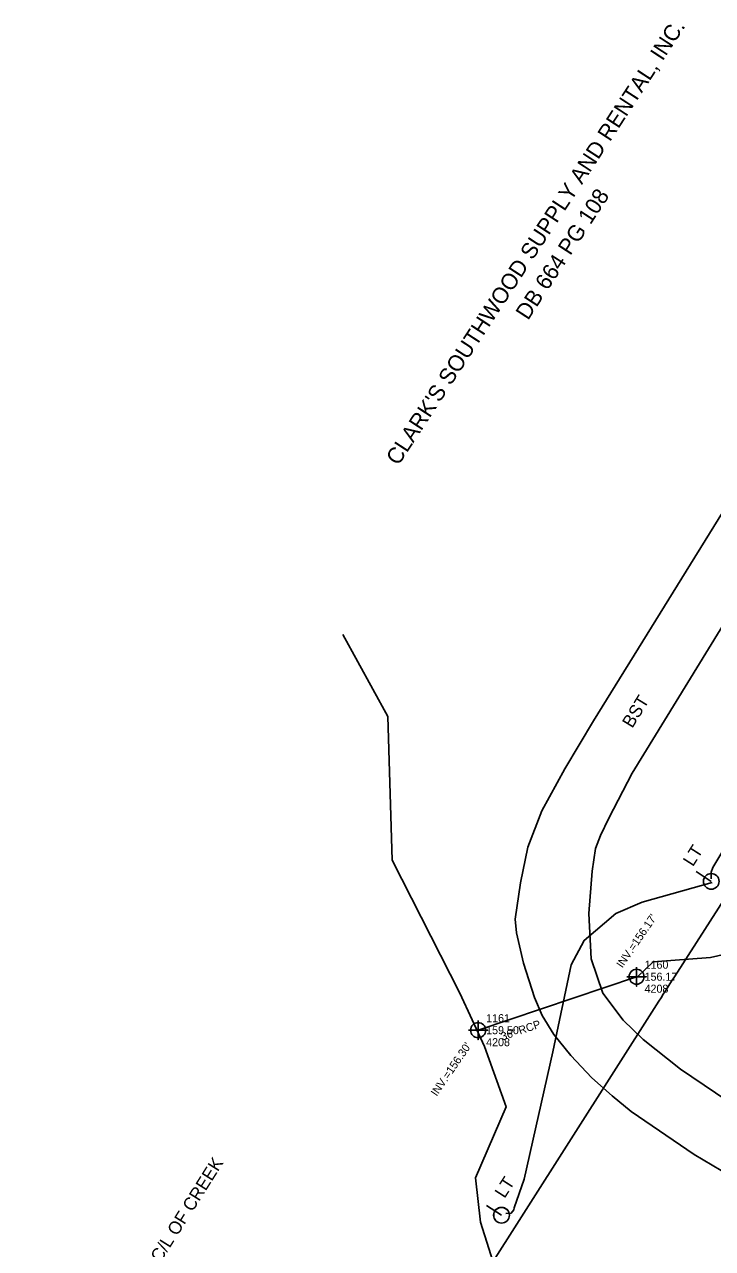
# Model space of a CAD drawing. Extents: x 1840200 to 1849051, y 348278 to 353012.
# Drawn here: x 1844547 to 1844762, y 350948.7 to 351331.2 of the extents above; entities that cross this region are included whole.
import ezdxf

# ---------------------------------------------------------------- set-up
doc = ezdxf.new("R2010")
doc.units = 0
for name, color, linetype in [('Default', 7, 'Continuous'), ('Exist Hydro Stream or Body of Water', 7, 'Continuous'), ('Exist Property Deed Book Text', 7, 'Continuous'), ('Exist Property Line Text', 7, 'Continuous'), ('Exist Property Owner Text', 7, 'Continuous'), ('Exist Right of Way Line', 7, 'Continuous'), ('Exist Roads EOP Other', 7, 'Continuous'), ('Exist Roads EOP Other Text', 7, 'Continuous'), ('Exist Structure Minor Pipes RCP 18 Inch SizeText', 7, 'Continuous'), ('Exist Structure Minor Pipes RCP 36 Inch', 7, 'Continuous'), ('Exist Structure Minor Pipes RCP 36 Inch Text', 7, 'Continuous'), ('Exist Structure Minor Pipes RCP 8 Inch Cogo Comment', 7, 'Continuous'), ('Exist Structure Minor Pipes RCP 8 Inch Cogo Elevation', 7, 'Continuous'), ('Exist Structure Minor Pipes RCP 8 Inch Cogo Number', 7, 'Continuous'), ('Exist Structure Minor Pipes RCP 8 Inch Cogo Point CELL', 7, 'Continuous'), ('Exist Utilities Other Pole CELL', 7, 'Continuous'), ('Exist Utilities Power Pole CELL', 7, 'Continuous'), ('Exist Utilities Power Pole Text', 7, 'Continuous'), ('Exist Utilities Power UG Cable SUE', 7, 'Continuous'), ('Exist Vegetation Woods Line', 7, 'Continuous')]:
    doc.layers.add(name, color=color, linetype=linetype)

# ---------------------------------------------------------------- blocks, each defined once
blk = doc.blocks.new('EXIST STRUCTURE MINOR PIPES RCP COGO POINT')
at = {"layer": 'Exist Structure Minor Pipes RCP 8 Inch Cogo Point CELL'}
blk.add_lwpolyline([(0, 0.06), (0, -0.06), (0, 0), (0.06, 0), (-0.06, 0)], dxfattribs=at)
blk.add_circle((0, 0), 0.0469, dxfattribs=at)
blk = doc.blocks.new('EXIST UTILITIES OTHER POLE')
at = {"layer": 'Exist Utilities Other Pole CELL'}
blk.add_circle((0, 0), 0.0493, dxfattribs=at)
blk = doc.blocks.new('EXIST UTILITIES POWER POLE')
at = {"layer": 'Exist Utilities Power Pole CELL'}
for q in [(0, 0.1125), (0, 0)]:
    blk.add_line((0, 0), q, dxfattribs=at)
blk.add_circle((0, 0), 0.049, dxfattribs=at)

msp = doc.modelspace()

# ---------------------------------------------------------------- linework, layer by layer
at = {"layer": 'Exist Hydro Stream or Body of Water'}
msp.add_lwpolyline([(1844738.66, 351033.74), (1844743.48, 351038.27), (1844761.39, 351039.68), (1844790.1, 351046.24), (1844810.62, 351053.12)], dxfattribs=at)
at = {"layer": 'Exist Right of Way Line'}
for p, q in [((1844750.11, 351033.62), (1844931.69, 351317.13)), ((1844331.22, 350376.7), (1844744.55, 351024.92))]:
    msp.add_line(p, q, dxfattribs=at)
msp.add_arc((1849048.13, 348280.84), 5104, 147.36144, 147.47735, dxfattribs=at)
at = {"layer": 'Exist Roads EOP Other'}
for points in [[(1844802.31, 350984.33), (1844795.67, 350984.44), (1844785.55, 350986.05), (1844777.75, 350987.41), (1844752.06, 351004.74), (1844740.33, 351014.05), (1844734.13, 351020.08), (1844727.74, 351028.47), (1844724.13, 351039.23), (1844723.34, 351053.39), (1844724.42, 351066.68), (1844725.49, 351073.74), (1844727.01, 351077.8), (1844729.61, 351083.21), (1844736.97, 351097.23), (1844764.42, 351142.02), (1844799.09, 351196.69), (1844831.77, 351248.29), (1844860.3, 351294.74), (1844872.48, 351313.36)], [(1844767.9, 351183.08), (1844724.85, 351113.66), (1844715.9, 351098.6), (1844708.72, 351085.53), (1844704.31, 351074.18), (1844702.01, 351062.98), (1844700.37, 351051.62), (1844700.73, 351047.39), (1844702.93, 351037.88), (1844706.37, 351027.18), (1844708.83, 351021.56), (1844712.45, 351015.59), (1844717.75, 351009.01), (1844724.36, 351002.07), (1844730.7, 350996.44), (1844736.64, 350991.51), (1844756.31, 350978.09), (1844770.37, 350969.74)]]:
    msp.add_lwpolyline(points, dxfattribs=at)
at = {"layer": 'Exist Structure Minor Pipes RCP 36 Inch'}
msp.add_lwpolyline([(1844688.79, 351016.95), (1844738.3, 351033.66)], dxfattribs=at)
at = {"layer": 'Exist Utilities Power UG Cable SUE'}
for points in [[(1844761.63, 351064.23), (1844761.64, 351066.37), (1844762.1, 351067.8), (1844792.74, 351118.67), (1844814.23, 351152.42), (1844837.11, 351187.76), (1844846.26, 351201.84), (1844847.96, 351203.97), (1844849.33, 351205.53)], [(1844697.46, 350959.67), (1844699.16, 350959.79), (1844699.9, 350960.82), (1844700.04, 350961.41), (1844703.13, 350970.35), (1844712.1, 351010.16), (1844717.85, 351037.39), (1844721.88, 351044.98), (1844731.85, 351053.42), (1844740.03, 351056.95), (1844761.92, 351063.12)]]:
    msp.add_lwpolyline(points, dxfattribs=at)
at = {"layer": 'Exist Vegetation Woods Line'}
msp.add_lwpolyline([(1844646.48, 351140.6), (1844660.62, 351114.96), (1844661.94, 351070.03), (1844683.12, 351028.55), (1844690.75, 351011.9), (1844697.55, 350993), (1844687.95, 350970.86), (1844689.48, 350956.93), (1844696.11, 350936.27), (1844708.08, 350920.13), (1844721.1, 350907.63), (1844735.15, 350896.02), (1844732.46, 350870.06), (1844723.35, 350853.35), (1844710.26, 350832.26), (1844679.51, 350804.43), (1844666.72, 350795.53), (1844655.26, 350795.9)], dxfattribs=at)

# ---------------------------------------------------------------- block references
at = {"layer": 'Default', "xscale": 50, "yscale": 50}
msp.add_blockref('EXIST UTILITIES OTHER POLE', (1844696.1, 350959.13), dxfattribs=at)
at = {"layer": 'Exist Structure Minor Pipes RCP 8 Inch Cogo Point CELL', "xscale": 50, "yscale": 50}
for p in [(1844738.3, 351033.66), (1844688.79, 351016.95)]:
    msp.add_blockref('EXIST STRUCTURE MINOR PIPES RCP COGO POINT', p, dxfattribs=at)
at = {"layer": 'Exist Utilities Power Pole CELL'}
for p, xscale, yscale, rotation in [((1844761.64, 351063.45), 50, 50, 57.17970670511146), ((1844696.1, 350959.13), 50.000000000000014, 50.00000000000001, 57.07723682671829)]:
    msp.add_blockref('EXIST UTILITIES POWER POLE', p, dxfattribs=dict(at, xscale=xscale, yscale=yscale, rotation=rotation))

# ---------------------------------------------------------------- texts
at = {"layer": 'Exist Property Deed Book Text'}
msp.add_text('DB 664 PG 108', height=5, rotation=56.8618, dxfattribs=at).set_placement((1844704.37, 351238.54))
at = {"layer": 'Exist Property Line Text'}
msp.add_text('PL IS C/L OF CREEK', height=4, rotation=57.765, dxfattribs=at).set_placement((1844581.75, 350931.82))
at = {"layer": 'Exist Property Owner Text'}
msp.add_text("CLARK'S SOUTHWOOD SUPPLY AND RENTAL, INC.", height=5, rotation=56.8618, dxfattribs=at).set_placement((1844663.86, 351193.12))
at = {"layer": 'Exist Roads EOP Other Text'}
msp.add_text('BST', height=4, rotation=58.4984, dxfattribs=at).set_placement((1844736.95, 351111.08))
at = {"layer": 'Exist Structure Minor Pipes RCP 18 Inch SizeText'}
for s, p in [("INV.=156.17'", (1844733.86, 351036.2)), ("INV.=156.30'", (1844675.86, 350996.11))]:
    msp.add_text(s, height=2.5, rotation=55.5112, dxfattribs=at).set_placement(p)
at = {"layer": 'Exist Structure Minor Pipes RCP 36 Inch Text'}
msp.add_text('36" RCP', height=2.5, rotation=18.6505, dxfattribs=at).set_placement((1844696.36, 351013.71))
at = {"layer": 'Exist Structure Minor Pipes RCP 8 Inch Cogo Comment'}
for p in [(1844740.8, 351028.66), (1844691.29, 351011.95)]:
    msp.add_text('4208', height=2.5, dxfattribs=at).set_placement(p)
at = {"layer": 'Exist Structure Minor Pipes RCP 8 Inch Cogo Elevation'}
for s, p in [('156.17', (1844740.8, 351032.41)), ('159.50', (1844691.29, 351015.7))]:
    msp.add_text(s, height=2.5, dxfattribs=at).set_placement(p)
at = {"layer": 'Exist Structure Minor Pipes RCP 8 Inch Cogo Number'}
for s, p in [('1160', (1844740.8, 351036.16)), ('1161', (1844691.29, 351019.45))]:
    msp.add_text(s, height=2.5, dxfattribs=at).set_placement(p)
at = {"layer": 'Exist Utilities Power Pole Text'}
for p in [(1844755.89, 351067.84), (1844697.05, 350964.18)]:
    msp.add_text('LT', height=4, rotation=57.4042, dxfattribs=at).set_placement(p)

doc.saveas('drawing.dxf')
